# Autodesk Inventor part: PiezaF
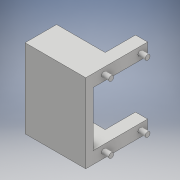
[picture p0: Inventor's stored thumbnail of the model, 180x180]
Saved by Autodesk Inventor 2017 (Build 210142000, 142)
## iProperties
Part Number: PiezaF
Material: Genérico
Document SubType Name: Modeling
Designer: Jaime
Density: 1 g/cm^3
Appearance: Valor por defecto
Author: Jaime
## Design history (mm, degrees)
sketch "Boceto1"
  geometry: L1 (0, 65)-(100, 65); L2 (100, 65)-(100, -65); L3 (100, -65)-(0, -65); L4 (0, -65)-(0, 65); 2 further points
  constraints: 8 end point, 2 parallel, 1 coincident, 1 horizontal, 1 midpoint, 1 perpendicular
  dimensions: "d0" = 100 distance of L2.end L3.end; "d1" = 130 distance of L1.end L2.end
extrude "Extrusión1" new body sketch "Boceto1" distance "d2" = 12; taper "d3" = 0 deg
sketch "Boceto2"
  geometry: L1 (-100, -65)-(0, -65) reference; L2 (-100, 65)-(-100, -65) reference; L3 (0, -65)-(-100, -65); L4 (-100, -65)-(-100, -45); L5 (-100, -45)-(0, -45); L6 (0, -45)-(0, -65); L7 (0, 65)-(-100, 65) reference; L8 (-100, 65)-(0, 65); L9 (0, 65)-(0, 45); L10 (0, 45)-(-100, 45); L11 (-100, 45)-(-100, 65); 1 further point
  constraints: 16 end point, 4 parallel, 2 horizontal, 2 perpendicular, 2 point on line
  dimensions: "d4" = 20 distance of L3.end L4.end; "d5" = 20 distance of L8.end L9.end
extrude "Extrusión2" join sketch "Boceto2" distance "d6" = 40; taper "d7" = 0 deg
sketch "Boceto3"
  geometry: L1 (-100, -65)-(0, -65) reference; L2 (0, -45)-(-100, -45) reference; L3 (0, -65)-(-20, -65); L4 (-20, -65)-(-20, -45); L5 (-20, -45)-(0, -45); L6 (0, -45)-(0, -65); L7 (-100, 65)-(0, 65) reference; L8 (0, 45)-(-100, 45) reference; L9 (0, 65)-(-20, 65); L10 (-20, 65)-(-20, 45); L11 (-20, 45)-(0, 45); L12 (0, 45)-(0, 65); 1 further point
  constraints: 16 end point, 4 parallel, 2 horizontal, 2 perpendicular, 2 point on line
  dimensions: "d8" = 20 distance of L4.end L5.end; "d9" = 20 distance of L11.end L10.end
extrude "Extrusión3" join sketch "Boceto3" distance "d10" = 50; taper "d11" = 0 deg
sketch "Boceto4"
  geometry: L1 (0, 102)-(20, 102) reference; L2 (20, 12)-(20, 102) reference; L3 (110, 12)-(110, 102) reference; C1 r 4 at (10, 90); C2 r 4 at (10, 30); C3 r 4 at (120, 90); C4 r 4 at (120, 30); 1 further point
  constraints: 4 centre point, 2 horizontal alignment, 2 vertical alignment
  dimensions: "d12" = 8 diameter of C1; "d13" = 8 diameter of C2; "d14" = 8 diameter of C3; "d15" = 8 diameter of C4; "d16" = 12 distance from line of L1 C1.centre; "d17" = 60 distance of C2.centre C1.centre; "d18" = 10 distance from line of L2 C1.centre; "d19" = 10 distance from line of L3 C3.centre
extrude "Extrusión4" join sketch "Boceto4" distance "d20" = 12; taper "d21" = 0 deg
node "Sólido1"
